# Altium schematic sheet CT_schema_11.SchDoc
size 147 x 119 mm
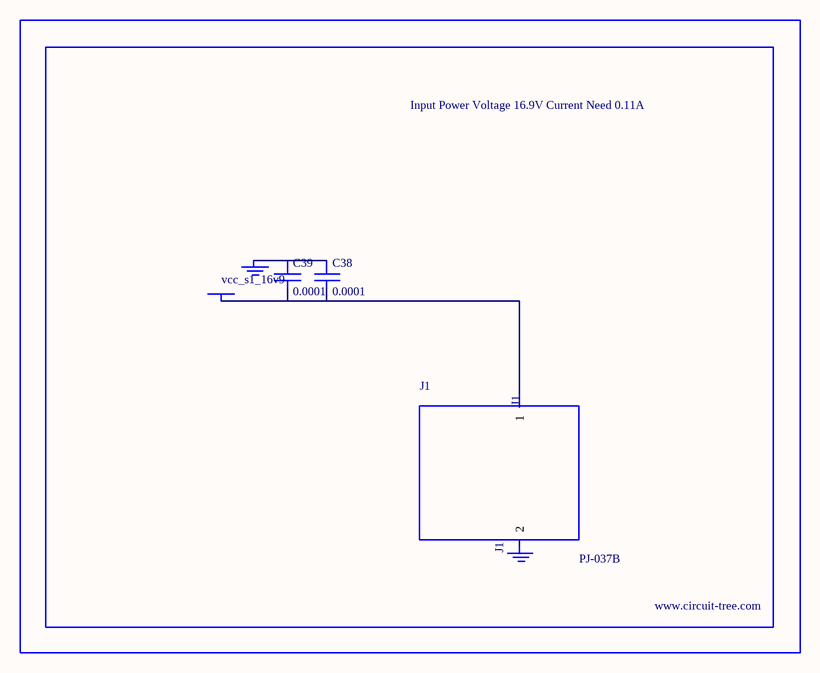
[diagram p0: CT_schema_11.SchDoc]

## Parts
BORDER10  (no value)
C38  0.0001  [EXV-9H]
C39  0.0001  [EXV-9H]
GND_INSTANCE_10_0  (no value)
GND_INSTANCE_10_1  (no value)
J1  PJ-037B  [PJ-037B_PACKAGE]
POWER_INSTANCE_10_0  vcc_s1_16v9

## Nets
NetC38_1: C38.1 C39.1 GND_INSTANCE_10_0.0(GND)
NetC38_2: C38.2 C39.2 J1.1 POWER_INSTANCE_10_0.0(PWR)

Not connected (* = marked no-connect by the designer): GND_INSTANCE_10_1 0(GND); J1 2

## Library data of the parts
BORDER10 = BORDER_PAGE10
C38 C39 = EDK107M035A9HAA
GND_INSTANCE_10_0 GND_INSTANCE_10_1 = GND
POWER_INSTANCE_10_0 = PWR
